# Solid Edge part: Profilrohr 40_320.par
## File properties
Username: ahadarics
Dokumentum tartalom típus: 0
Author: ahadarics
Last saved by: ahadarics
Revision: 87
Sűrűség: 0,000 kg/m^3
Pontosság: 0,990
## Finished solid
Body 1: solid body, 175 faces, 519 edges, 346 vertices.
  Faces by surface: cylinder 107, plane 68
  Edges by curve: line 305, circle 214
Bounding box of the edges (mm): 51.354 x 51.354 x 363.000, from (-25.6768, -25.6768, -329) to (25.6768, 25.6768, 34).
Cylindrical faces by radius (mm): R0.1 x16, R0.2 x30, R0.5 x28, R1 x8, R2.7 x8, R3.5 x4, R5 x4, R20 x1, R22 x8
Planar faces by outward normal: +x 6, +y 6, +z 1, -x 4, -y 4, -z 1, oblique 46
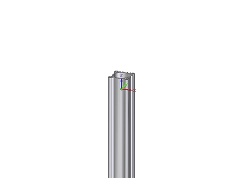
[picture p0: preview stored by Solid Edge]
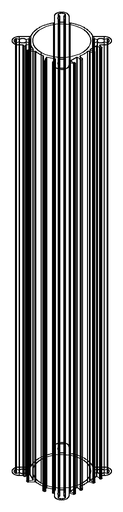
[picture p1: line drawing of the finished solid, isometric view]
